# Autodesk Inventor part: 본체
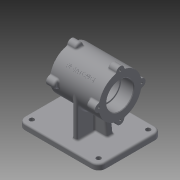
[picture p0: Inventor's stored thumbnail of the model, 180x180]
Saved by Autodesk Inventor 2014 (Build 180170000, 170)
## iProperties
Created: 2015-12
Part Number: 본체
Material: 일반
Document SubType Name: Modeling
Designer: aapexcom
Density: 1 g/cm^3
Appearance: 기본값
Author: aapexcom
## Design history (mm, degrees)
sketch "스케치1"
  geometry: L1 (-70, 55)-(70, 55); L2 (70, 55)-(70, -55); L3 (70, -55)-(-70, -55); L4 (-70, -55)-(-70, 55); 1 further point
  constraints: 8 end point, 2 parallel, 1 horizontal, 1 perpendicular
  dimensions: "d0" = 140 distance of L2.end L3.end; "d1" = 110 distance of L1.end L2.end; "d2" = 55 distance from line of L1 point (0, 0) (= 0.5 x d1); "d3" = 70 distance from line of point (0, 0) L2 (= 0.5 x d0)
extrude "돌출1" new body sketch "스케치1" distance "d4" = 10; taper "d5" = 0 deg
fillet "모깎기1" dims "d6" = 12
sketch "스케치2"
  geometry: C1 r 4 at (-58, 43); C2 r 4 at (-58, -43); C3 r 4 at (58, -43); C4 r 4 at (58, 43); A1 r 12 centre (-58, 43) between (-58, 55) and (-70, 43) reference; A2 r 12 centre (-58, -43) between (-70, -43) and (-58, -55) reference; A3 r 12 centre (58, -43) between (58, -55) and (70, -43) reference; A4 r 12 centre (58, 43) between (70, 43) and (58, 55) reference; 1 further point
  constraints: 4 centre point, 4 coincident
  dimensions: "d7" = 8 diameter of C1; "d8" = 8 diameter of C2; "d9" = 8 diameter of C3; "d10" = 8 diameter of C4
extrude "돌출2" cut sketch "스케치2" stored distance "d11" = 10; taper "d12" = 0 deg
node "작업 평면1"
sketch "스케치4"
  geometry: L1 (98, 0)-(-12, 0) reference; L2 (-12, 0)-(-12, 10) reference; L3 (-12, 10)-(98, 10) reference; L4 (98, 10)-(98, 0) reference; L5 (6, 10)-(80, 10); L6 (80, 10)-(80, 80); L7 (80, 80)-(6, 80); L8 (6, 80)-(6, 10); 1 further point
  constraints: 8 end point, 2 parallel, 1 horizontal, 1 perpendicular, 1 point on line
  dimensions: "d14" = 70 distance of L5.end L6.end; "d15" = 74 distance of L6.end L7.end; "d16" = 37 distance from line of point (43, 0) L6 (= 0.5 x d15)
extrude "돌출3" join sketch "스케치4" stored distance "d17" = 8; taper "d18" = 0 deg
sketch "스케치5"
  geometry: L1 (70, 10)-(70, 0) reference; L2 (70, 0)-(-70, 0) reference; L3 (-70, 0)-(-70, 10) reference; L4 (-70, 10)-(-14, 10) reference; L5 (-14, 10)-(-14, 80) reference; L6 (-14, 80)-(-6, 80) reference; L7 (-6, 80)-(-6, 10) reference; L8 (-6, 10)-(70, 10) reference; L9 (-35, 10)-(-26.329, 80.616); L10 (15, 10)-(6.329, 80.616); L11 (-10, 80)-(-10, 0); L12 (-26.329, 80.616)-(6.329, 80.616); L13 (-35, 10)-(15, 10); 1 further point
  constraints: 10 end point, 3 point on line, 2 perpendicular, 1 collinear, 1 midpoint
  dimensions: "d19" = 97 deg angle of L4 L9; "d20" = 97 deg angle of L10 L8; "d21" = 25 horizontal distance of L11.end L10.start; "d22" = 25 horizontal distance of L9.start L11.end
extrude "돌출4" join sketch "스케치5" stored distance "d23" = 12; taper "d24" = 0 deg
node "작업 평면2"
sketch "스케치6"
  geometry: L1 (0, 0)-(86, 0) reference; C1 r 37 at (43, 80); 1 further point
  constraints: 1 centre point, 1 vertical alignment
  dimensions: "d26" = 74 diameter of C1; "d27" = 80 distance from line of L1 C1.centre
extrude "돌출5" join sketch "스케치6" distance "d28" = 85; taper "d29" = 0 deg
sketch "스케치7"
  geometry: C1 r 37 at (0, 0) reference; C2 r 23.5 at (0, 0); 1 further point
  constraints: 1 centre point, 1 coincident
  dimensions: "d30" = 47 diameter of C2
extrude "돌출6" cut sketch "스케치7" distance "d31" = 22; taper "d32" = 0 deg
chamfer "모따기1" distance "d33" = 1; stored, may be unused: second distance "d34" = 2, angle "d35" = 45 deg
fillet "모깎기2" dims "d36" = 0.3
sketch "스케치8"
  geometry: C1 r 37 at (0, 0) reference; C2 r 23.5 at (0, 0); 1 further point
  constraints: 1 centre point, 1 coincident
  dimensions: "d37" = 47 diameter of C2
extrude "돌출7" cut sketch "스케치8" distance "d38" = 22; taper "d39" = 0 deg
chamfer "모따기2" distance "d40" = 1; stored, may be unused: second distance "d41" = 2, angle "d42" = 45 deg
fillet "모깎기3" dims "d43" = 0.3
sketch "스케치9"
  geometry: C1 r 23.2 at (0, 0) reference; C2 r 21 at (0, 0); 1 further point
  constraints: 1 centre point, 1 coincident
  dimensions: "d44" = 42 diameter of C2
extrude "돌출8" cut sketch "스케치9" distance "d45" = 41; taper "d46" = 0 deg
sketch "스케치10"
  geometry: L1 (80, 55)-(80, -55) reference; L2 (80, -55)-(70, -55) reference; L3 (70, -55)-(70, 55) reference; L4 (70, 55)-(80, 55) reference; C1 r 24.5 at (0, 0) reference; C2 r 37 at (0, 0) reference; C3 r 37 at (0, 0) reference; C4 r 24.5 at (0, 0) reference; C5 r 7 at (-37, 0.001); C6 r 7 at (-0.017, -37); C7 r 7 at (-0.001, 37); C8 r 7 at (37, 0.001); 1 further point
  constraints: 4 centre point
  dimensions: "d47" = 14 diameter of C5; "d48" = 14 diameter of C6; "d50" = 14 diameter of C7; "d51" = 14 diameter of C8
extrude "돌출9" join sketch "스케치10" distance "d52" = 15; taper "d53" = 0 deg
sketch "스케치11"
  geometry: C1 r 7 at (37, 0.001); C2 r 7 at (0.017, -37); C3 r 7 at (-37, 0.001); C4 r 7 at (0.001, 37); A1 r 37 centre (0, 0) between (36.338, -6.968) and (36.338, 6.969) reference; A2 r 7 centre (37, 0.001) between (36.338, -6.968) and (36.338, 6.969) reference; A3 r 37 centre (0, 0) between (6.97, 36.338) and (-6.967, 36.338) reference; A4 r 7 centre (0.001, 37) between (6.97, 36.338) and (-6.967, 36.338) reference; A5 r 37 centre (0, 0) between (-6.952, -36.341) and (6.985, -36.335) reference; A6 r 7 centre (0.017, -37) between (-6.952, -36.341) and (6.985, -36.335) reference; A7 r 7 centre (-37, 0.001) between (-36.338, 6.97) and (-36.338, -6.967) reference; 1 further point
  constraints: 4 centre point, 4 coincident
  dimensions: "d54" = 14 diameter of C1; "d55" = 14 diameter of C2; "d56" = 14 diameter of C3; "d57" = 14 diameter of C4
extrude "돌출10" join sketch "스케치11" distance "d58" = 15; taper "d59" = 0 deg
sketch "스케치12"
  geometry: A1 r 7 centre (-80.001, 80) between (-73.033, 79.338) and (-86.97, 79.338) reference; A2 r 7 centre (-117, 43.001) between (-116.338, 49.969) and (-116.338, 36.032) reference; A3 r 7 centre (-80.017, 6) between (-86.985, 6.665) and (-73.048, 6.659) reference; A4 r 7 centre (-43, 43.001) between (-43.662, 36.033) and (-43.662, 49.97) reference; 5 further points
  constraints: 4 coincident
hole "구멍1" sketch "스케치12" at (-80.001, 80), (-117, 43.001), (-43, 43.001), (-80.017, 6) diameter "d60" = 3.242; stored, may be unused: countersink angle "d64" = 90 deg, drill point angle "d66" = 118 deg; dims "d61" = 9, "d62" = 4, "d63" = 2, "d65" = 11
sketch "스케치13"
  geometry: A1 r 7 centre (43, 43.001) between (43.662, 49.97) and (43.662, 36.033) reference; A2 r 7 centre (80.017, 6) between (73.048, 6.659) and (86.985, 6.665) reference; A3 r 7 centre (117, 43.001) between (116.338, 36.032) and (116.338, 49.969) reference; A4 r 7 centre (80.001, 80) between (86.97, 79.338) and (73.033, 79.338) reference; 5 further points
  constraints: 4 coincident
hole "구멍2" sketch "스케치13" at (80.001, 80), (117, 43.001), (80.017, 6), (43, 43.001) diameter "d67" = 3.242; stored, may be unused: countersink angle "d71" = 90 deg, drill point angle "d73" = 118 deg; dims "d68" = 9, "d69" = 4, "d70" = 2, "d72" = 11
fillet "모깎기4" dims "d74" = 3
fillet "모깎기5" dims "d75" = 3
fillet "모깎기6" dims "d76" = 3
fillet "모깎기7" dims "d77" = 3
sketch "스케치14"
  geometry: L1 (-30.5, 56.8)-(-30.5, 59) reference; L2 (-30.5, 59)-(10.5, 59) reference; L3 (10.5, 59)-(10.5, 56.8) reference; L4 (10.8, 56.5)-(31.5, 56.5) reference; L5 (31.5, 56.5)-(32.5, 55.5) reference; L6 (32.5, 55.5)-(32.5, 44.621) reference; L7 (32.5, 44.621)-(21.5, 44.621) reference; L8 (21.5, 41.379)-(32.5, 41.379) reference; L9 (32.5, 41.379)-(32.5, 36) reference; L10 (32.5, 36)-(20.5, 36) reference; L11 (17.5, 39)-(17.5, 40) reference; L12 (14.5, 43)-(14.339, 43) reference; L13 (11.361, 39.634)-(14.677, 12.634) reference; L14 (17.654, 10)-(67, 10) reference; L15 (70, 7)-(70, 0) reference; L16 (70, 0)-(-70, 0) reference; L17 (-70, 0)-(-70, 7) reference; L18 (-67, 10)-(-37.654, 10) reference; L19 (-34.677, 12.634)-(-31.361, 39.634) reference; L20 (-34.339, 43)-(-34.5, 43) reference; L21 (-37.5, 40)-(-37.5, 39) reference; L22 (-40.5, 36)-(-52.5, 36) reference; L23 (-52.5, 36)-(-52.5, 41.379) reference; L24 (-52.5, 41.379)-(-41.5, 41.379) reference; L25 (-41.5, 44.621)-(-52.5, 44.621) reference; L26 (-52.5, 44.621)-(-52.5, 55.5) reference; L27 (-52.5, 55.5)-(-51.5, 56.5) reference; L28 (-51.5, 56.5)-(-30.8, 56.5) reference; L29 (-30.8, 103.5)-(-51.5, 103.5) reference; L30 (-51.5, 103.5)-(-52.5, 104.5) reference; L31 (-52.5, 104.5)-(-52.5, 115.379) reference; L32 (-52.5, 115.379)-(-41.5, 115.379) reference; L33 (-41.5, 118.621)-(-52.5, 118.621) reference; L34 (-52.5, 118.621)-(-52.5, 124) reference; L35 (-52.5, 124)-(-40.5, 124) reference; L36 (-37.5, 121)-(-37.5, 120) reference; L37 (-34.5, 117)-(14.5, 117) reference; L38 (17.5, 120)-(17.5, 121) reference; L39 (20.5, 124)-(32.5, 124) reference; L40 (32.5, 124)-(32.5, 118.621) reference; L41 (32.5, 118.621)-(21.5, 118.621) reference; L42 (21.5, 115.379)-(32.5, 115.379) reference; L43 (32.5, 115.379)-(32.5, 104.5) reference; L44 (32.5, 104.5)-(31.5, 103.5) reference; L45 (31.5, 103.5)-(10.8, 103.5) reference; L46 (10.5, 103.2)-(10.5, 101) reference; L47 (10.5, 101)-(-30.5, 101) reference; L48 (-30.5, 101)-(-30.5, 103.2) reference; L49 (-10, 0)-(-10, 117); L50 (-52.5, 104.5)-(-52.5, 55.5) reference; L51 (-52.5, 80)-(-10, 80); L52 (-52.5, 80)-(-71.352, 80); A1 r 0.3 centre (-30.8, 56.8) between (-30.8, 56.5) and (-30.5, 56.8) reference; A2 r 0.3 centre (10.8, 56.8) between (10.5, 56.8) and (10.8, 56.5) reference; A3 r 3 centre (14.5, 40) between (17.5, 40) and (14.5, 43) reference; A4 r 3 centre (17.654, 13) between (14.677, 12.634) and (17.654, 10) reference; A5 r 3 centre (67, 7) between (70, 7) and (67, 10) reference; A6 r 3 centre (-67, 7) between (-67, 10) and (-70, 7) reference; A7 r 3 centre (-37.654, 13) between (-37.654, 10) and (-34.677, 12.634) reference; A8 r 3 centre (-34.5, 40) between (-34.5, 43) and (-37.5, 40) reference; A9 r 0.3 centre (-30.8, 103.2) between (-30.5, 103.2) and (-30.8, 103.5) reference; A10 r 3 centre (-34.5, 120) between (-37.5, 120) and (-34.5, 117) reference; A11 r 3 centre (14.5, 120) between (14.5, 117) and (17.5, 120) reference; A12 r 0.3 centre (10.8, 103.2) between (10.8, 103.5) and (10.5, 103.2) reference; 1 further point
  constraints: 6 end point, 4 vertical alignment, 2 midpoint, 2 point on line, 1 collinear, 1 perpendicular, 6 other
  node "절단 모서리 투영4"
node "작업 평면4"
  node "작업 평면3"
sketch "스케치15"
  geometry: L1 (-85, 18.922)-(-85, -18.907) reference; 3 further points
  constraints: 1 horizontal alignment, 1 midpoint, 1 other
  dimensions: "d80" = 42.5 distance from line of L1 point (-42.5, 0.007)
feature "엠보싱1" sketch "스케치15" dims "d0" = 140, "d1" = 110, "d2" = 55 (= 0.5 x d1), "d3" = 70 (= 0.5 x d0), "d81" = 0.5, "d82" = 0
node "솔리드1"
node "투영된 루프1"
node "투영된 루프2"
node "투영된 루프3"
node "절단 모서리 투영1"
node "절단 모서리 투영2"
node "절단 모서리 투영3"
other parameters: "d25" = 42.5, "d78" = -45 deg
